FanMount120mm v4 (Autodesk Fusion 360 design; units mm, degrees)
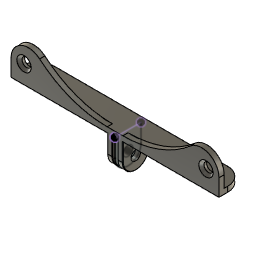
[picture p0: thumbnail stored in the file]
sketch "Sketch1" plane through (0, 0, 0) normal (0, 1, 0) x axis (1, 0, 0)
  line L1 (60, 0) -> (-60, 0)
  line L2 (60, -60) -> (60, 0)
  line L3 (-60, -60) -> (60, -60)
  line L4 (-60, 0) -> (-60, -60)
  line L5 (60, 3) -> (60, 0)
  line L6 (-60, 3) -> (60, 3)
  line L7 (-60, 0) -> (-60, 3)
  circle C1 centre (-52.5, -7.5) radius 2.65
  circle C2 centre (52.5, -7.5) radius 2.65
  circle C3 centre (0, -60) radius 63
  point P6 (0, 0)
  point P1 (0, 0)
  point P7 (-52.5, -7.5)
  point P8 (52.5, -7.5)
  point P9 (0, -60)
  point P2 (-60, 0)
  point P3 (60, 0)
  horizontal L1
  vertical L2
  horizontal L3
  vertical L4
  midpoint L1 P6
  coincident P1 P6
  horizontal P7 P8
  vertical P6 P9
  coincident L3 P9
  perpendicular L1 L5
  perpendicular L2 L6
  vertical L7
  dimension "d1" distance P2 P3 = 120
  dimension "d2" distance L1 P7 = 7.5 (= "( ( 120 - 105 ) / 2 ) * 1 mm")
  dimension "d3" distance P7 P8 = 105
  dimension "d4" distance P1 P8 = 52.5 (= "( 105 / 2 ) * 1 mm")
  dimension "d5" diameter C1 = 5.3
  dimension "d6" diameter C2 = 5.3
  dimension "d7" diameter C3 = 126 (= "63 mm * 2")
  dimension "d8" distance P6 P9 = 60 (= "( 120 / 2 ) * 1 mm")
  dimension "d9" distance L1 L6 = 3
extrude "Extrude1" new body sketch "Sketch1" profile of L1 L2 L4 C1 C2 C3 L5 L6 L7 along normal blind 3
extrude "Extrude2" add sketch "Sketch1" profile of L1 C3 L5 L6 L7 along normal blind 15
fillet "Fillet1" radius 10
fillet "Fillet2" radius 60
sketch "Sketch2" plane through (0, 0, 0) normal (1, 0, 0) x axis (0, 1, 0)
  line L1 (0, -13.5) -> (0, -3)
  line L2 (15, -3) -> (15, -13.5)
  line L3 (15, -3) -> (0, -3)
  arc A1 centre (7.5, -13.5) radius 7.5 clockwise from (15, -13.5) to (0, -13.5)
  circle C1 centre (7.5, -13.5) radius 2.75
  point P2 (0, -3)
  point P3 (0, -3)
  point P7 (15, -3)
  coincident P2 P3
  vertical L1
  tangent L1 A1
  tangent A1 L2
  parallel L1 L2
  coincident P7 L3
  concentric A1 C1
  dimension "d18" = 18
  dimension "d19" distance L1 L2 = 15
  dimension "d20" diameter C1 = 5.5
extrude "Extrude3" add sketch "Sketch2" blind 3 from offset 1.5
extrude "Extrude4" add sketch "Sketch2" blind -3 from offset -1.5
fillet "Fillet3" radius 10
chamfer "Chamfer1" distance 0.3
chamfer "Chamfer2" distance 1.5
